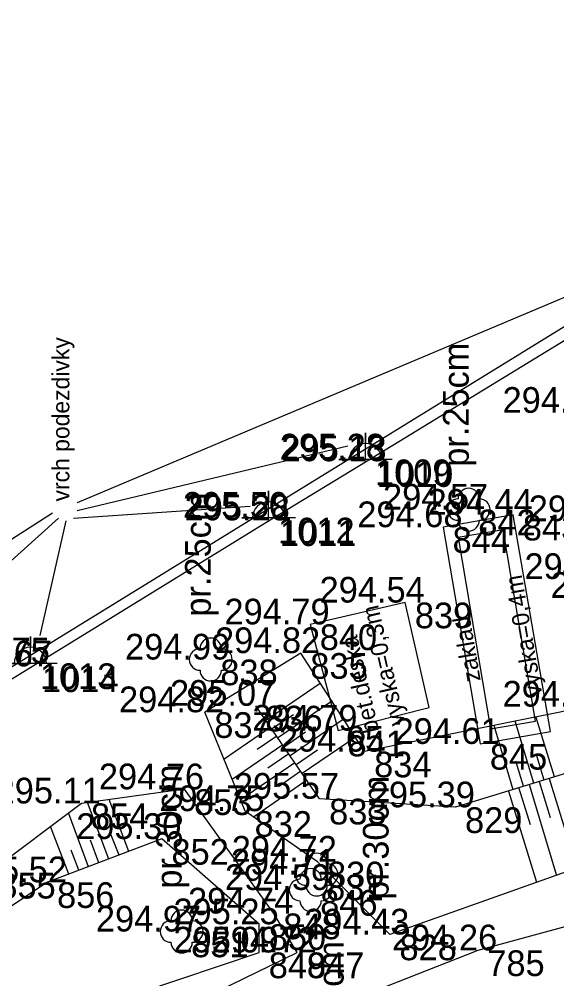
# Model space of a CAD drawing. Extents: x -599970 to -599524, y -1154772 to -1154457.
# Drawn here: x -599765.66 to -599753.11, y -1154619.91 to -1154597.51 of the extents above; entities that cross this region are included whole.
import ezdxf

# ---------------------------------------------------------------- set-up
doc = ezdxf.new("R2010")
doc.units = 0
for name, color, linetype in [('Z-KATASTRALNI MAPA', 7, 'Continuous'), ('Z-PLOT DRATENY', 7, 'Continuous'), ('Z-PODROBNE BODY', 7, 'Continuous'), ('Z-PODROBNE BODY-CISLO', 7, 'Continuous'), ('Z-PODROBNE BODY-VYSKA', 7, 'Continuous'), ('Z-POPISY OBJEKTU A ZPEVNENYCH PLOCH', 7, 'Continuous'), ('Z-PRUMERY KMENU STROMU', 7, 'Continuous'), ('Z-SCHODY', 7, 'Continuous'), ('Z-SRAFOVANI SVAHU', 7, 'Continuous'), ('Z-STROMY ZNACKY KULTUR', 7, 'Continuous'), ('Z-TERENNI HRANY PATY', 7, 'Continuous'), ('Z-VYSKOVE BODY', 7, 'Continuous'), ('Z-ZPEVNENE PLOCHY', 7, 'Continuous')]:
    doc.layers.add(name, color=color, linetype=linetype)

msp = doc.modelspace()

# ---------------------------------------------------------------- linework, layer by layer
at = {"layer": 'Z-KATASTRALNI MAPA'}
msp.add_line((-599741.29, -1154597.51), (-599768.28, -1154614.14), dxfattribs=at)
at = {"layer": 'Z-PLOT DRATENY'}
msp.add_lwpolyline([(-599741.2, -1154597.57), (-599748.19, -1154602.02), (-599750.03, -1154603.24), (-599757.54, -1154607.83), (-599759.8, -1154609.21), (-599765.35, -1154612.62), (-599767.84, -1154614.15), (-599771.68, -1154615.78), (-599777.02, -1154618.08), (-599780.14, -1154619.26), (-599783.61, -1154619.05), (-599791.83, -1154621.49)], dxfattribs=at)
at = {"layer": 'Z-PODROBNE BODY'}
for p, q in [((-599757.58, -1154607.79), (-599757.58, -1154607.79)), ((-599757.54, -1154607.83), (-599757.54, -1154607.83)), ((-599755.17, -1154608.96), (-599755.17, -1154608.96)), ((-599759.84, -1154609.15), (-599759.84, -1154609.15)), ((-599759.8, -1154609.21), (-599759.8, -1154609.21)), ((-599754.13, -1154609.08), (-599754.13, -1154609.08)), ((-599755.77, -1154609.37), (-599755.77, -1154609.37)), ((-599756.65, -1154611.13), (-599756.65, -1154611.13)), ((-599758.87, -1154611.64), (-599758.87, -1154611.64)), ((-599759.09, -1154612.31), (-599759.09, -1154612.31)), ((-599765.4, -1154612.55), (-599765.4, -1154612.55)), ((-599765.35, -1154612.62), (-599765.35, -1154612.62)), ((-599761.19, -1154612.46), (-599761.19, -1154612.46)), ((-599761.33, -1154613.69), (-599761.33, -1154613.69)), ((-599760.14, -1154613.54), (-599760.14, -1154613.54)), ((-599758.22, -1154614.12), (-599758.22, -1154614.12)), ((-599754.9, -1154614.43), (-599754.9, -1154614.43)), ((-599757.6, -1154614.61), (-599757.6, -1154614.61)), ((-599761.8, -1154615.49), (-599761.8, -1154615.49)), ((-599758.65, -1154615.71), (-599758.65, -1154615.71)), ((-599764.21, -1154615.82), (-599764.21, -1154615.82)), ((-599755.48, -1154615.91), (-599755.48, -1154615.91)), ((-599760.39, -1154616), (-599760.39, -1154616)), ((-599762.33, -1154616.65), (-599762.33, -1154616.65)), ((-599758.7, -1154617.18), (-599758.7, -1154617.18)), ((-599758.72, -1154617.48), (-599758.72, -1154617.48)), ((-599765, -1154617.66), (-599765, -1154617.66)), ((-599758.86, -1154617.84), (-599758.86, -1154617.84)), ((-599759.72, -1154618.39), (-599759.72, -1154618.39)), ((-599760.06, -1154618.64), (-599760.06, -1154618.64)), ((-599761.87, -1154618.81), (-599761.87, -1154618.81)), ((-599757.01, -1154618.88), (-599757.01, -1154618.88)), ((-599760.06, -1154619.3), (-599760.06, -1154619.3)), ((-599759.17, -1154619.3), (-599759.17, -1154619.3)), ((-599754.96, -1154619.25), (-599754.96, -1154619.25))]:
    msp.add_line(p, q, dxfattribs=at)
at = {"layer": 'Z-SRAFOVANI SVAHU'}
for points in [[(-599759.91, -1154613.88), (-599758.64, -1154613.01)], [(-599759.63, -1154614.29), (-599758.37, -1154613.43)], [(-599759.77, -1154614.08), (-599759.26, -1154613.74)], [(-599759.34, -1154614.7), (-599758.1, -1154613.85)], [(-599753.65, -1154615.35), (-599754.09, -1154613.9)], [(-599753.17, -1154615.2), (-599753.6, -1154613.81)], [(-599759.79, -1154614.04), (-599760.88, -1154614.79)], [(-599759.48, -1154614.5), (-599758.98, -1154614.15)], [(-599754.13, -1154615.5), (-599754.58, -1154614)], [(-599759.65, -1154614.25), (-599760.11, -1154614.56)], [(-599759.06, -1154615.11), (-599757.82, -1154614.27)], [(-599759.51, -1154614.45), (-599760.69, -1154615.26)], [(-599759.2, -1154614.91), (-599758.7, -1154614.57)], [(-599759.23, -1154614.87), (-599760.5, -1154615.74)], [(-599759.37, -1154614.66), (-599759.86, -1154615)], [(-599753.89, -1154615.42), (-599754.07, -1154614.83)], [(-599753.41, -1154615.28), (-599753.58, -1154614.71)], [(-599759.09, -1154615.07), (-599759.61, -1154615.43)], [(-599758.95, -1154615.28), (-599760.19, -1154616.14)], [(-599753.53, -1154615.31), (-599753.27, -1154616.15)], [(-599753.29, -1154615.24), (-599752.65, -1154617.33)], [(-599754.24, -1154615.53), (-599753.59, -1154617.66)], [(-599754, -1154615.46), (-599753.74, -1154616.31)], [(-599753.76, -1154615.38), (-599753.12, -1154617.5)], [(-599763.1, -1154616.94), (-599763.56, -1154615.73)], [(-599763.57, -1154617.12), (-599764.07, -1154615.8)], [(-599764.04, -1154617.3), (-599764.51, -1154616.04)], [(-599764.5, -1154617.47), (-599764.93, -1154616.36)], [(-599763.33, -1154617.03), (-599763.53, -1154616.52)], [(-599763.8, -1154617.21), (-599764, -1154616.68)], [(-599764.27, -1154617.38), (-599764.45, -1154616.91)]]:
    msp.add_lwpolyline(points, dxfattribs=at)
at = {"layer": 'Z-STROMY ZNACKY KULTUR'}
for centre in [(-599755.17, -1154608.96), (-599761.19, -1154612.46), (-599758.72, -1154617.48), (-599758.86, -1154617.84), (-599761.87, -1154618.81)]:
    msp.add_circle(centre, 0.00025, dxfattribs=at)
for centre, start, end in [((-599755.17, -1154608.71), 0, 180), ((-599755.42, -1154608.96), 90, 270), ((-599754.92, -1154608.96), 270, 90), ((-599755.17, -1154609.21), 180, 360), ((-599761.19, -1154612.21), 0, 180), ((-599761.44, -1154612.46), 90, 270), ((-599760.94, -1154612.46), 270, 90), ((-599761.19, -1154612.71), 180, 360), ((-599758.72, -1154617.23), 0, 180), ((-599758.97, -1154617.48), 90, 270), ((-599758.86, -1154617.59), 0, 180), ((-599758.47, -1154617.48), 270, 90), ((-599759.11, -1154617.84), 90, 270), ((-599758.72, -1154617.73), 180, 360), ((-599758.61, -1154617.84), 270, 90), ((-599758.86, -1154618.09), 180, 360), ((-599761.87, -1154618.56), 0, 180), ((-599762.12, -1154618.81), 90, 270), ((-599761.62, -1154618.81), 270, 90), ((-599761.87, -1154619.06), 180, 360)]:
    msp.add_arc(centre, 0.25, start, end, dxfattribs=at)
at = {"layer": 'Z-TERENNI HRANY PATY'}
for points in [[(-599749.54, -1154610.89), (-599751.87, -1154610.58), (-599752.38, -1154613.56), (-599757.6, -1154614.61), (-599759.09, -1154612.31), (-599761.33, -1154613.69)], [(-599750.67, -1154610.69), (-599750.88, -1154614.5), (-599755.48, -1154615.91), (-599758.65, -1154615.71), (-599760.14, -1154613.54)], [(-599749.54, -1154610.89), (-599749.59, -1154616.24), (-599757.01, -1154618.88), (-599758.7, -1154617.18), (-599760.39, -1154616), (-599761.33, -1154613.69)], [(-599759.17, -1154619.3), (-599759.72, -1154618.39), (-599761.8, -1154615.49), (-599764.21, -1154615.82), (-599766.37, -1154617.44), (-599767.34, -1154617.74), (-599772.76, -1154620.37), (-599773.78, -1154623.48), (-599771.1, -1154626.66), (-599770.56, -1154628.5), (-599767.6, -1154637.96), (-599764.82, -1154638.47)], [(-599760.06, -1154619.3), (-599760.06, -1154618.64), (-599762.33, -1154616.65), (-599765, -1154617.66), (-599767.23, -1154619.14), (-599772.56, -1154623.16), (-599769.35, -1154628.39), (-599766.8, -1154637.11), (-599765.7, -1154637.36), (-599764.13, -1154628.13), (-599766.55, -1154621.48), (-599760.06, -1154619.3)], [(-599762.25, -1154627.96), (-599765.06, -1154622.17), (-599759.17, -1154619.3)]]:
    msp.add_lwpolyline(points, dxfattribs=at)
at = {"layer": 'Z-VYSKOVE BODY'}
for p, q in [((-599764.3, -1154608.79), (-599750.7, -1154603.06)), ((-599757.58, -1154607.165), (-599757.58, -1154607.415)), ((-599757.58, -1154607.415), (-599757.58, -1154607.165)), ((-599757.58, -1154607.79), (-599757.58, -1154607.165)), ((-599757.58, -1154607.165), (-599757.58, -1154607.415)), ((-599764.31, -1154608.98), (-599757.99, -1154607.47)), ((-599756.955, -1154607.79), (-599758.205, -1154607.79)), ((-599758.205, -1154607.79), (-599757.58, -1154607.79)), ((-599756.955, -1154607.79), (-599757.58, -1154607.79)), ((-599759.84, -1154608.525), (-599759.84, -1154608.775)), ((-599759.84, -1154608.775), (-599759.84, -1154608.525)), ((-599759.84, -1154609.15), (-599759.84, -1154608.525)), ((-599759.84, -1154608.525), (-599759.84, -1154608.775)), ((-599764.88, -1154609.04), (-599779.75, -1154618.62)), ((-599764.39, -1154609.16), (-599760.27, -1154608.88)), ((-599764.74, -1154609.16), (-599771.47, -1154615.19)), ((-599764.57, -1154609.22), (-599765.18, -1154611.9)), ((-599759.215, -1154609.15), (-599760.465, -1154609.15)), ((-599760.465, -1154609.15), (-599759.84, -1154609.15)), ((-599759.215, -1154609.15), (-599759.84, -1154609.15)), ((-599765.4, -1154611.925), (-599765.4, -1154612.175)), ((-599765.4, -1154612.175), (-599765.4, -1154611.925)), ((-599765.4, -1154612.55), (-599765.4, -1154611.925)), ((-599765.4, -1154611.925), (-599765.4, -1154612.175)), ((-599764.775, -1154612.55), (-599766.025, -1154612.55)), ((-599766.025, -1154612.55), (-599765.4, -1154612.55)), ((-599764.775, -1154612.55), (-599765.4, -1154612.55))]:
    msp.add_line(p, q, dxfattribs=at)
for centre, start, end in [((-599757.58, -1154607.79), 90, 180), ((-599757.58, -1154607.79), 0, 90), ((-599759.84, -1154609.15), 90, 180), ((-599759.84, -1154609.15), 0, 90), ((-599765.4, -1154612.55), 90, 180), ((-599765.4, -1154612.55), 0, 90)]:
    msp.add_arc(centre, 0.375, start, end, dxfattribs=at)
at = {"layer": 'Z-ZPEVNENE PLOCHY'}
for points in [[(-599671.02, -1154617.03), (-599671.63, -1154613.35), (-599675.05, -1154613.45), (-599680.32, -1154612.41), (-599686.62, -1154610.91), (-599694.45, -1154609.33), (-599700.34, -1154608.57), (-599705.79, -1154608.71), (-599715.78, -1154610.69), (-599725.58, -1154612.61), (-599730.02, -1154613.49), (-599735.64, -1154614.56), (-599743.95, -1154616.26), (-599754.96, -1154619.25), (-599762.63, -1154622.27), (-599761.65, -1154625.43)], [(-599754.13, -1154609.08), (-599755.77, -1154609.37), (-599754.9, -1154614.43), (-599753.26, -1154614.14), (-599754.13, -1154609.08)], [(-599756.65, -1154611.13), (-599758.87, -1154611.64), (-599758.22, -1154614.12), (-599756.09, -1154613.58), (-599756.65, -1154611.13)]]:
    msp.add_lwpolyline(points, dxfattribs=at)
msp.add_lwpolyline([(-599754.37, -1154609.43), (-599755.42, -1154609.61), (-599754.66, -1154614.08), (-599753.61, -1154613.9)], close=True, dxfattribs=at)

# ---------------------------------------------------------------- texts
at = {"layer": 'Z-PODROBNE BODY-CISLO'}
for s, p in [(' 1009', (-599757.58, -1154608.39)), (' 1010', (-599757.54, -1154608.43)), (' 842', (-599755.17, -1154609.56)), (' 1012', (-599759.84, -1154609.75)), (' 1011', (-599759.8, -1154609.81)), (' 843', (-599754.13, -1154609.68)), (' 844', (-599755.77, -1154609.97)), (' 839', (-599756.65, -1154611.73)), (' 840', (-599758.87, -1154612.24)), (' 835', (-599759.09, -1154612.91)), (' 1013', (-599765.4, -1154613.15)), (' 1014', (-599765.35, -1154613.22)), (' 838', (-599761.19, -1154613.06)), (' 836', (-599760.14, -1154614.14)), (' 837', (-599761.33, -1154614.29)), (' 841', (-599758.22, -1154614.72)), (' 845', (-599754.9, -1154615.03)), (' 834', (-599757.6, -1154615.21)), (' 853', (-599761.8, -1154616.09)), (' 833', (-599758.65, -1154616.31)), (' 854', (-599764.21, -1154616.42)), (' 832', (-599760.39, -1154616.6)), (' 829', (-599755.48, -1154616.51)), (' 852', (-599762.33, -1154617.25)), (' 830', (-599758.7, -1154617.78)), (' 855', (-599766.37, -1154618.04)), (' 831', (-599758.72, -1154618.08)), (' 856', (-599765, -1154618.26)), (' 846', (-599758.86, -1154618.44)), (' 848', (-599759.72, -1154618.99)), (' 850', (-599760.06, -1154619.24)), (' 851', (-599761.87, -1154619.41)), (' 828', (-599757.01, -1154619.48)), (' 849', (-599760.06, -1154619.9)), (' 847', (-599759.17, -1154619.9)), (' 785', (-599754.96, -1154619.85))]:
    msp.add_text(s, height=0.6, dxfattribs=at).set_placement(p)
at = {"layer": 'Z-PODROBNE BODY-VYSKA'}
for s, p in [('294.54 ', (-599754.38, -1154606.7)), ('295.28 ', (-599759.58, -1154607.79)), ('295.13 ', (-599759.54, -1154607.83)), ('294.57 ', (-599757.17, -1154608.96)), ('295.50 ', (-599761.84, -1154609.15)), ('295.28 ', (-599761.8, -1154609.21)), ('294.44 ', (-599756.13, -1154609.08)), ('294.68 ', (-599757.77, -1154609.37)), ('294.28 ', (-599753.77, -1154609.23)), ('294.19 ', (-599753.87, -1154610.58)), ('294.54 ', (-599758.65, -1154611.13)), ('294.03 ', (-599753.26, -1154611.02)), ('294.79 ', (-599760.87, -1154611.64)), ('294.82 ', (-599761.09, -1154612.31)), ('295.75 ', (-599767.4, -1154612.55)), ('294.99 ', (-599763.19, -1154612.46)), ('295.67 ', (-599767.35, -1154612.62)), ('294.82 ', (-599763.33, -1154613.69)), ('295.07 ', (-599762.14, -1154613.54)), ('294.24 ', (-599754.38, -1154613.56)), ('294.79 ', (-599760.22, -1154614.12)), ('294.61 ', (-599756.9, -1154614.43)), ('294.65 ', (-599759.6, -1154614.61)), ('294.76 ', (-599763.8, -1154615.49)), ('295.57 ', (-599760.65, -1154615.71)), ('295.11 ', (-599766.21, -1154615.82)), ('295.39 ', (-599757.48, -1154615.91)), ('294.75 ', (-599762.39, -1154616)), ('295.30 ', (-599764.33, -1154616.65)), ('294.72 ', (-599760.7, -1154617.18)), ('294.71 ', (-599760.72, -1154617.48)), ('295.52 ', (-599767, -1154617.66)), ('294.59 ', (-599760.86, -1154617.84)), ('294.74 ', (-599761.72, -1154618.39)), ('294.97 ', (-599763.87, -1154618.81)), ('295.25 ', (-599762.06, -1154618.64)), ('294.43 ', (-599759.01, -1154618.88)), ('294.26 ', (-599756.96, -1154619.25)), ('295.09 ', (-599762.06, -1154619.3)), ('294.72 ', (-599761.17, -1154619.3))]:
    msp.add_text(s, height=0.6, dxfattribs=at).set_placement(p)
at = {"layer": 'Z-POPISY OBJEKTU A ZPEVNENYCH PLOCH'}
msp.add_text('zaklad', height=0.4, rotation=99.6493, dxfattribs=at).set_placement((-599754.89, -1154612.95))
at = {"layer": 'Z-PRUMERY KMENU STROMU'}
for s, p in [('pr.25cm', (-599755.17, -1154607.96)), ('pr.25cm', (-599761.19, -1154611.46)), ('pr.30cm', (-599761.87, -1154617.81)), ('pr.30cm', (-599757.04, -1154618.07)), ('pr.30cm', (-599758.09, -1154621.93))]:
    msp.add_text(s, height=0.6, rotation=90, dxfattribs=at).set_placement(p)
at = {"layer": 'Z-SCHODY'}
for s, rotation, p in [('vyska=0,4m', 99.7559, (-599753.45, -1154613.29)), ('vyska=0,3m', 102.875, (-599756.65, -1154613.96)), ('bet.deska', 102.875, (-599757.26, -1154614.13))]:
    msp.add_text(s, height=0.4, rotation=rotation, dxfattribs=at).set_placement(p)
at = {"layer": 'Z-VYSKOVE BODY'}
msp.add_text('vrch podezdivky', height=0.4, rotation=90, dxfattribs=at).set_placement((-599764.49, -1154608.77))

doc.saveas('drawing.dxf')
